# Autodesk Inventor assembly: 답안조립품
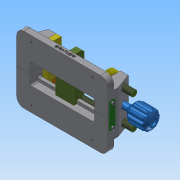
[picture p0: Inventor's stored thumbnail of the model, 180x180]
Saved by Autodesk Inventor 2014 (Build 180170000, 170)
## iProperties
Created: 2018-03
Part Number: 답안조립품
Document SubType Name: Assembly
Designer: NET
Mass: 1034.81 g
Surface Area: 918.509 cm^2
Volume: 340.421 cm^3
Density: 3.03979 g/cm^3
Author: NET
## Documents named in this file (10)
- C:\Users\NET\Desktop\380307V1020\답안조립품.iam
- C:\Users\NET\Desktop\380307V1020\바이스본체 A.ipt
- C:\Users\NET\Desktop\380307V1020\바이스본체 B.ipt
- C:\Users\NET\Desktop\380307V1020\고정 플레이트.ipt
- C:\Users\NET\Desktop\380307V1020\십자오목머리나사 M3.ipt
- C:\Users\NET\Desktop\380307V1020\지지대.ipt
- C:\Users\NET\Desktop\380307V1020\십자오목머리나사 M4.ipt
- C:\Users\NET\Desktop\380307V1020\슬라이딩 부품.ipt
- C:\Users\NET\Desktop\380307V1020\스퍼기어.ipt
- C:\Users\NET\Desktop\380307V1020\핸들.ipt
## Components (3 placed, 2 different names)
1. 고정 플레이트:1
2. 고정 플레이트:2
3. 핸들:1 — 각도:1
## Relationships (1: Angle 1)
- 각도:1 [Angle]: 핸들:1
